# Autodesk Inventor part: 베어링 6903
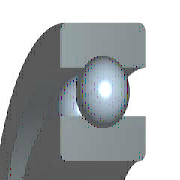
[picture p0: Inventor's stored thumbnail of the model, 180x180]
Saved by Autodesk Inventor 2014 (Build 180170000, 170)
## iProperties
Created: 2012-02
Part Number: 베어링 6903
Material: 강철, 연강
Description: 깊은 그루브 볼 베어링
Document SubType Name: Modeling
Standard: KS B 2023
Designer: mduedu
Standards Organization: KS
Language: ko-KR
Size Designation: 6003 - 17 x 35 x 10
Categories: <MemberInstance><Categories><Category DisplayName="샤프트 부품" InternalName="7f7aeb1f-a693-4053-b835-cee3144e0d98" Mnemonic="SHFT"><Category DisplayName="베어링" Inter
Density: 7.86 g/cm^3
Mass: 17.7898 g
Surface Area: 30.969 cm^2
Volume: 2.26333 cm^3
Appearance: 터키옥색
IsCustomPart: 1
Author: mduedu
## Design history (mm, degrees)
sketch "스케치" dims "d0" = 3.38 (= -0.26 x WD + 0.26 x BD)
  geometry: L1 (1.81, 11.75)-(5.19, 11.75); L2 (3.5, 11.75)-(3.5, 10.06); L3 (3.5, 11.75)-(3.5, 13.44); L4 (2.244, 10.619)-(0, 10.619); L5 (0, 8.5)-(7, 8.5); L6 (2.244, 12.881)-(0, 12.881); L7 (0, 15)-(7, 15); L8 (7, 8.5)-(7, 10.619); L9 (4.756, 10.619)-(7, 10.619); L10 (4.756, 12.881)-(7, 12.881); L11 (7, 15)-(7, 12.881); L12 (-2, 0)-(12, 0) reference; L13 (0, 7.2)-(0, 16.3) reference; 1 other entity
  constraints: 22 end point, 4 point on line, 2 collinear, 2 perpendicular, 2 symmetric about line, 1 midpoint, 1 parallel, 14 other
  dimensions: "d9" = 17 diameter of L5 L12 (= WD); "d11" = 30 diameter of L7 L12 (= BD); "d12" = 7 distance between parallel lines of L8 L13 (= KB); "d13" = 21.238 diameter of L9 L12 (= 0.326 x BD + 0.674 x WD)
revolve "본체" stored, may be unused: angle "d6" = 90 deg
revolve "볼" stored, may be unused: angle "d7" = 90 deg
pattern_circular "IDS_ARRAYBALL[SIMPL:T]" dims angle "d3" = 360 deg
body "Solid1"
fillet "모깎기1" dims "d1" = 0.3 (= KRS)
other parameters: "WD" = 17 [user parameter; used in 5 equation terms], "BD" = 30 [user parameter; used in 5 equation terms], "KB" = 7 [user parameter; used in 1 equation term], "KRS" = 0.3 [user parameter; used in 1 equation term], "d4" = 0, "d5" = 0, "d8" = 0, "d14" = 0, "d15" = 0, "BBA" = 0 [user parameter], "BC0" = 3250000 [user parameter], "BC" = 6050000 [user parameter], "BR" = 15 (= 0.5 x BD) [user parameter], "WR" = 8.5 (= 0.5 x WD) [user parameter]
